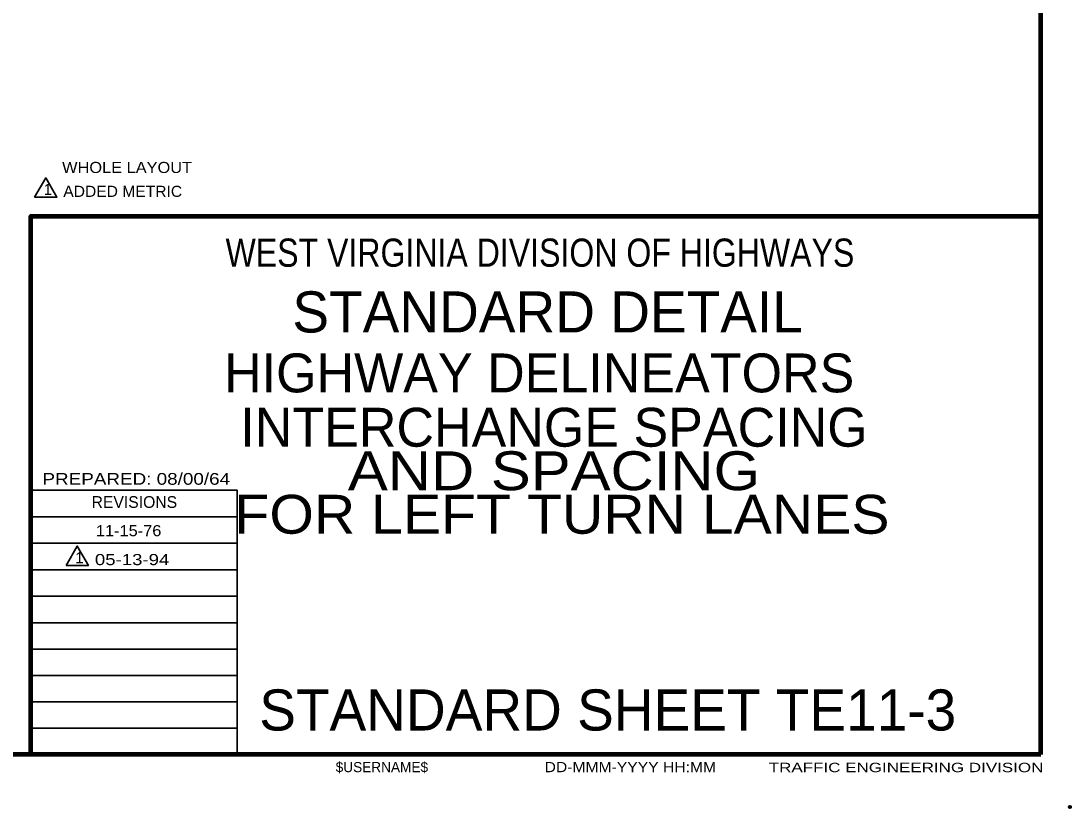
# Model space of a CAD drawing. Extents: x 393 to 1249, y -102 to 530.
# Drawn here: x 1022 to 1248.7, y -14.4 to 155.6 of the extents above; entities that cross this region are included whole.
import ezdxf
from ezdxf.enums import TextEntityAlignment as Align

# ---------------------------------------------------------------- set-up
doc = ezdxf.new("R2010")
doc.units = 0
doc.header["$LTSCALE"] = 0.97
doc.header["$PDMODE"] = 32
doc.header["$PDSIZE"] = 0.485
doc.layers.add('1', color=7, linetype='Continuous', lineweight=40)
doc.layers.add('61', color=7, linetype='Continuous', lineweight=35)

msp = doc.modelspace()

# ---------------------------------------------------------------- linework, layer by layer
at = {"layer": '1', "lineweight": 158}
for q in [(1242.1684, 523.2155), (1242.1684, 113.4155), (450.5684, -2.8845)]:
    msp.add_line((1242.1684, -2.8845), q, dxfattribs=at)
at = {"layer": '1', "lineweight": 13}
msp.add_line((1242.1684, -2.8845), (1242.1684, 523.2155), dxfattribs=at)
at = {"layer": '1', "lineweight": 35}
for p, q in [((1068.6684, 48.5155), (1024.1684, 48.5155)), ((1068.6684, 42.8155), (1024.1684, 42.8155)), ((1068.6684, 37.0155), (1024.1684, 37.0155)), ((1068.6684, 31.3155), (1024.1684, 31.3155)), ((1068.6684, 25.6155), (1024.1684, 25.6155)), ((1068.6684, 19.9155), (1024.1684, 19.9155)), ((1068.6684, 14.2155), (1024.1684, 14.2155)), ((1068.6684, 8.5155), (1024.1684, 8.5155)), ((1068.6684, 2.8155), (1024.1684, 2.8155))]:
    msp.add_line(p, q, dxfattribs=at)
for points in [[(1024.975, 117.5529), (1027.375, 121.7099), (1029.7749, 117.5529)], [(1031.7953, 37.9965), (1034.1953, 42.1535), (1036.5952, 37.9965)]]:
    msp.add_lwpolyline(points, close=True, dxfattribs=at)
at = {"layer": '1', "lineweight": 158}
msp.add_lwpolyline([(1024.1684, -2.8845), (1024.1684, 113.4155), (1242.1684, 113.4155)], dxfattribs=at)
at = {"layer": '1', "lineweight": 35}
msp.add_lwpolyline([(1068.6684, -2.8845), (1068.6684, 54.2155), (1024.1684, 54.2155)], dxfattribs=at)
at = {"layer": '1'}
msp.add_point((1248.4684, -14.1845), dxfattribs=at)
at = {"layer": '61', "lineweight": 53}
for q in [(1089.4684, -2.8845), (1089.4684, -2.8845), (1089.4684, -2.8845), (1089.7684, -2.8845), (1089.7684, -2.8845)]:
    msp.add_line((1242.1684, -2.8845), q, dxfattribs=at)

# ---------------------------------------------------------------- texts
at = {"layer": '1'}
for s, height, width, p in [('WHOLE LAYOUT', 2.4, 1.1, (1030.9122, 122.7664)), ('ADDED METRIC', 2.4, 1.05, (1031.1701, 117.6062)), ('PREPARED: 08/00/64', 2.537, 1.2, (1026.6684, 55.4155)), ('11-15-76', 2.4, 1.1, (1038.2081, 44.297)), ('05-13-94', 2.4, 1.25, (1037.9904, 38.0498)), ('DD-MMM-YYYY HH:MM', 2.2, 1.15, (1135.0684, -6.6845)), ('TRAFFIC ENGINEERING DIVISION', 2.031, 1.35, (1183.4684, -6.6845))]:
    msp.add_text(s, height=height, dxfattribs=dict(at, width=width)).set_placement(p)
for s, height, p in [('1', 2.4, (1026.9451, 118.0117)), ('REVISIONS', 2.537, (1037.2684, 50.4155)), ('1', 2.4, (1033.7654, 38.4553)), ('STANDARD SHEET TE11-3', 8.881, (1073.4684, 2.3155)), ('$USERNAME$', 2.2, (1089.9684, -6.6845))]:
    msp.add_text(s, height=height, dxfattribs=at).set_placement(p)
for s, height, width, p in [('WEST VIRGINIA DIVISION OF HIGHWAYS', 6.089, 0.85, (1134.0684, 102.5155)), (' AND SPACING ', 8.4, 1.15, (1137.1028, 54.2386)), (' FOR LEFT TURN LANES', 8.4, 1.1, (1137.1028, 44.8386))]:
    msp.add_text(s, height=height, dxfattribs=dict(at, width=width)).set_placement(p, align=Align.CENTER)
for s, height, p in [('STANDARD DETAIL', 8.881, (1135.7184, 88.3155)), ('HIGHWAY DELINEATORS', 8.4, (1133.9002, 75.3773)), ('INTERCHANGE SPACING', 8.4, (1137.1028, 63.6386))]:
    msp.add_text(s, height=height, dxfattribs=at).set_placement(p, align=Align.CENTER)

doc.saveas('drawing.dxf')
